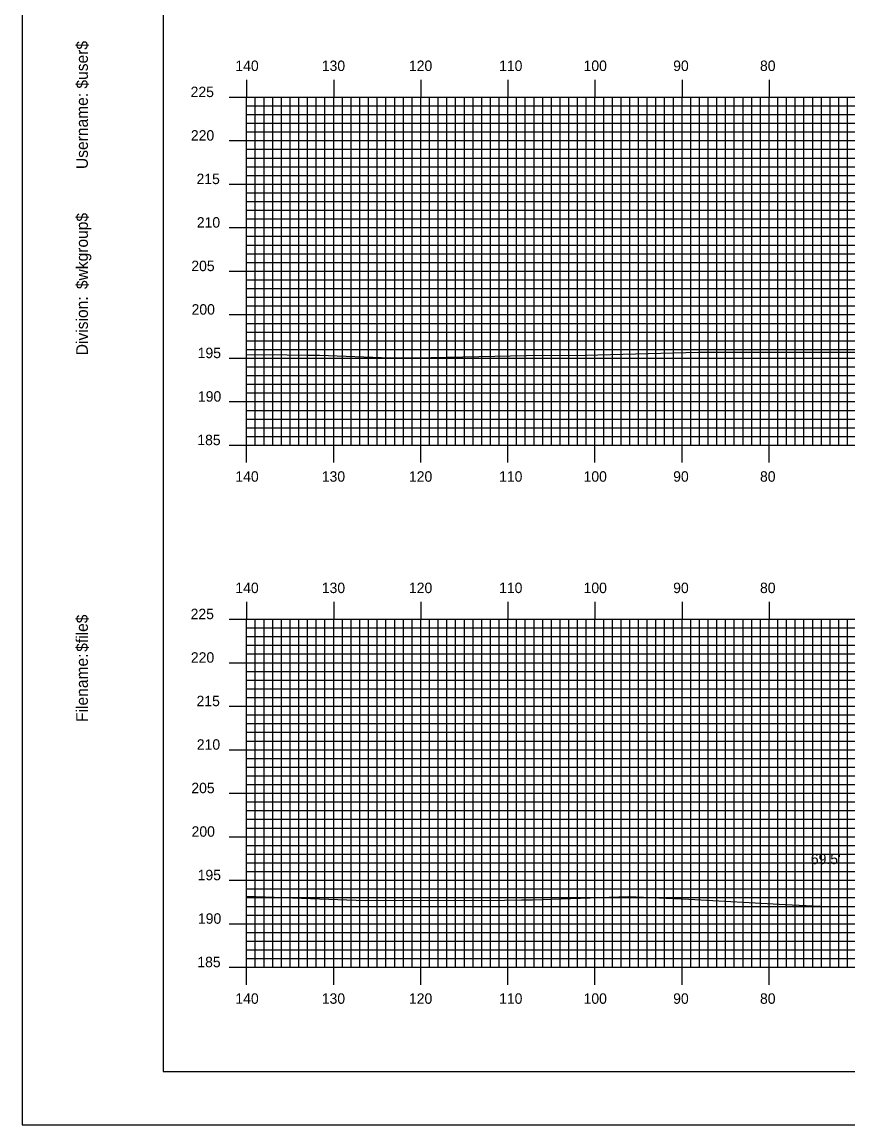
# Model space of a CAD drawing. Extents: x 1811374 to 1811717, y 442591 to 442811.
# Drawn here: x 1811373.6 to 1811468.4, y 442590.5 to 442717.3 of the extents above; entities that cross this region are included whole.
import ezdxf

# ---------------------------------------------------------------- set-up
doc = ezdxf.new("R2010")
doc.units = 0
for name, color, linetype in [('BORDER', 7, 'Continuous'), ('D_Text_Standard', 7, 'Continuous'), ('H_V ANNOTATION', 7, 'Continuous'), ('MAJOR', 7, 'Continuous'), ('MINOR', 7, 'Continuous'), ('PLOT BOUNDARY', 7, 'Continuous'), ('S_Roadway_Centerline', 7, 'Continuous')]:
    doc.layers.add(name, color=color, linetype=linetype)

msp = doc.modelspace()

# ---------------------------------------------------------------- linework, layer by layer
at = {"layer": 'BORDER'}
msp.add_lwpolyline([(1811389.8, 442596.67), (1811709.8, 442596.67), (1811709.8, 442806.67), (1811389.8, 442806.67)], close=True, dxfattribs=at)
at = {"layer": 'MAJOR'}
for p, q in [((1811399.4, 442710.67), (1811399.4, 442708.67)), ((1811409.4, 442710.67), (1811409.4, 442708.67)), ((1811419.4, 442710.67), (1811419.4, 442708.67)), ((1811429.4, 442710.67), (1811429.4, 442708.67)), ((1811439.4, 442710.67), (1811439.4, 442708.67)), ((1811449.4, 442710.67), (1811449.4, 442708.67)), ((1811459.4, 442710.67), (1811459.4, 442708.67)), ((1811397.4, 442708.67), (1811399.4, 442708.67)), ((1811399.4, 442708.67), (1811679.4, 442708.67)), ((1811399.4, 442668.67), (1811399.4, 442708.67)), ((1811399.4, 442668.67), (1811399.4, 442708.67)), ((1811399.4, 442708.67), (1811679.4, 442708.67)), ((1811409.4, 442668.67), (1811409.4, 442708.67)), ((1811419.4, 442668.67), (1811419.4, 442708.67)), ((1811429.4, 442668.67), (1811429.4, 442708.67)), ((1811439.4, 442668.67), (1811439.4, 442708.67)), ((1811449.4, 442668.67), (1811449.4, 442708.67)), ((1811459.4, 442668.67), (1811459.4, 442708.67)), ((1811397.4, 442703.67), (1811399.4, 442703.67)), ((1811399.4, 442703.67), (1811679.4, 442703.67)), ((1811397.4, 442698.67), (1811399.4, 442698.67)), ((1811399.4, 442698.67), (1811679.4, 442698.67)), ((1811397.4, 442693.67), (1811399.4, 442693.67)), ((1811399.4, 442693.67), (1811679.4, 442693.67)), ((1811397.4, 442688.67), (1811399.4, 442688.67)), ((1811399.4, 442688.67), (1811679.4, 442688.67)), ((1811397.4, 442683.67), (1811399.4, 442683.67)), ((1811399.4, 442683.67), (1811679.4, 442683.67)), ((1811397.4, 442678.67), (1811399.4, 442678.67)), ((1811399.4, 442678.67), (1811679.4, 442678.67)), ((1811397.4, 442673.67), (1811399.4, 442673.67)), ((1811399.4, 442673.67), (1811679.4, 442673.67)), ((1811397.4, 442668.67), (1811399.4, 442668.67)), ((1811399.4, 442668.67), (1811679.4, 442668.67)), ((1811399.4, 442668.67), (1811679.4, 442668.67)), ((1811399.4, 442666.66), (1811399.4, 442668.67)), ((1811409.4, 442666.66), (1811409.4, 442668.67)), ((1811419.4, 442666.66), (1811419.4, 442668.67)), ((1811429.4, 442666.66), (1811429.4, 442668.67)), ((1811439.4, 442666.66), (1811439.4, 442668.67)), ((1811449.4, 442666.66), (1811449.4, 442668.67)), ((1811459.4, 442666.66), (1811459.4, 442668.67)), ((1811399.4, 442650.67), (1811399.4, 442648.67)), ((1811409.4, 442650.67), (1811409.4, 442648.67)), ((1811419.4, 442650.67), (1811419.4, 442648.67)), ((1811429.4, 442650.67), (1811429.4, 442648.67)), ((1811439.4, 442650.67), (1811439.4, 442648.67)), ((1811449.4, 442650.67), (1811449.4, 442648.67)), ((1811459.4, 442650.67), (1811459.4, 442648.67)), ((1811397.4, 442648.67), (1811399.4, 442648.67)), ((1811399.4, 442648.67), (1811679.4, 442648.67)), ((1811399.4, 442608.67), (1811399.4, 442648.67)), ((1811399.4, 442608.67), (1811399.4, 442648.67)), ((1811399.4, 442648.67), (1811679.4, 442648.67)), ((1811409.4, 442608.67), (1811409.4, 442648.67)), ((1811419.4, 442608.67), (1811419.4, 442648.67)), ((1811429.4, 442608.67), (1811429.4, 442648.67)), ((1811439.4, 442608.67), (1811439.4, 442648.67)), ((1811449.4, 442608.67), (1811449.4, 442648.67)), ((1811459.4, 442608.67), (1811459.4, 442648.67)), ((1811397.4, 442643.67), (1811399.4, 442643.67)), ((1811399.4, 442643.67), (1811679.4, 442643.67)), ((1811397.4, 442638.67), (1811399.4, 442638.67)), ((1811399.4, 442638.67), (1811679.4, 442638.67)), ((1811397.4, 442633.67), (1811399.4, 442633.67)), ((1811399.4, 442633.67), (1811679.4, 442633.67)), ((1811397.4, 442628.67), (1811399.4, 442628.67)), ((1811399.4, 442628.67), (1811679.4, 442628.67)), ((1811397.4, 442623.67), (1811399.4, 442623.67)), ((1811399.4, 442623.67), (1811679.4, 442623.67)), ((1811397.4, 442618.67), (1811399.4, 442618.67)), ((1811399.4, 442618.67), (1811679.4, 442618.67)), ((1811397.4, 442613.67), (1811399.4, 442613.67)), ((1811399.4, 442613.67), (1811679.4, 442613.67)), ((1811397.4, 442608.67), (1811399.4, 442608.67)), ((1811399.4, 442608.67), (1811679.4, 442608.67)), ((1811399.4, 442608.67), (1811679.4, 442608.67)), ((1811399.4, 442606.66), (1811399.4, 442608.67)), ((1811409.4, 442606.66), (1811409.4, 442608.67)), ((1811419.4, 442606.66), (1811419.4, 442608.67)), ((1811429.4, 442606.66), (1811429.4, 442608.67)), ((1811439.4, 442606.66), (1811439.4, 442608.67)), ((1811449.4, 442606.66), (1811449.4, 442608.67)), ((1811459.4, 442606.66), (1811459.4, 442608.67))]:
    msp.add_line(p, q, dxfattribs=at)
at = {"layer": 'MINOR'}
for p, q in [((1811400.4, 442668.67), (1811400.4, 442708.67)), ((1811401.4, 442668.67), (1811401.4, 442708.67)), ((1811402.4, 442668.67), (1811402.4, 442708.67)), ((1811403.4, 442668.67), (1811403.4, 442708.67)), ((1811404.4, 442668.67), (1811404.4, 442708.67)), ((1811405.4, 442668.67), (1811405.4, 442708.67)), ((1811406.4, 442668.67), (1811406.4, 442708.67)), ((1811407.4, 442668.67), (1811407.4, 442708.67)), ((1811408.4, 442668.67), (1811408.4, 442708.67)), ((1811410.4, 442668.67), (1811410.4, 442708.67)), ((1811411.4, 442668.67), (1811411.4, 442708.67)), ((1811412.4, 442668.67), (1811412.4, 442708.67)), ((1811413.4, 442668.67), (1811413.4, 442708.67)), ((1811414.4, 442668.67), (1811414.4, 442708.67)), ((1811415.4, 442668.67), (1811415.4, 442708.67)), ((1811416.4, 442668.67), (1811416.4, 442708.67)), ((1811417.4, 442668.67), (1811417.4, 442708.67)), ((1811418.4, 442668.67), (1811418.4, 442708.67)), ((1811420.4, 442668.67), (1811420.4, 442708.67)), ((1811421.4, 442668.67), (1811421.4, 442708.67)), ((1811422.4, 442668.67), (1811422.4, 442708.67)), ((1811423.4, 442668.67), (1811423.4, 442708.67)), ((1811424.4, 442668.67), (1811424.4, 442708.67)), ((1811425.4, 442668.67), (1811425.4, 442708.67)), ((1811426.4, 442668.67), (1811426.4, 442708.67)), ((1811427.4, 442668.67), (1811427.4, 442708.67)), ((1811428.4, 442668.67), (1811428.4, 442708.67)), ((1811430.4, 442668.67), (1811430.4, 442708.67)), ((1811431.4, 442668.67), (1811431.4, 442708.67)), ((1811432.4, 442668.67), (1811432.4, 442708.67)), ((1811433.4, 442668.67), (1811433.4, 442708.67)), ((1811434.4, 442668.67), (1811434.4, 442708.67)), ((1811435.4, 442668.67), (1811435.4, 442708.67)), ((1811436.4, 442668.67), (1811436.4, 442708.67)), ((1811437.4, 442668.67), (1811437.4, 442708.67)), ((1811438.4, 442668.67), (1811438.4, 442708.67)), ((1811440.4, 442668.67), (1811440.4, 442708.67)), ((1811441.4, 442668.67), (1811441.4, 442708.67)), ((1811442.4, 442668.67), (1811442.4, 442708.67)), ((1811443.4, 442668.67), (1811443.4, 442708.67)), ((1811444.4, 442668.67), (1811444.4, 442708.67)), ((1811445.4, 442668.67), (1811445.4, 442708.67)), ((1811446.4, 442668.67), (1811446.4, 442708.67)), ((1811447.4, 442668.67), (1811447.4, 442708.67)), ((1811448.4, 442668.67), (1811448.4, 442708.67)), ((1811450.4, 442668.67), (1811450.4, 442708.67)), ((1811451.4, 442668.67), (1811451.4, 442708.67)), ((1811452.4, 442668.67), (1811452.4, 442708.67)), ((1811453.4, 442668.67), (1811453.4, 442708.67)), ((1811454.4, 442668.67), (1811454.4, 442708.67)), ((1811455.4, 442668.67), (1811455.4, 442708.67)), ((1811456.4, 442668.67), (1811456.4, 442708.67)), ((1811457.4, 442668.67), (1811457.4, 442708.67)), ((1811458.4, 442668.67), (1811458.4, 442708.67)), ((1811460.4, 442668.67), (1811460.4, 442708.67)), ((1811461.4, 442668.67), (1811461.4, 442708.67)), ((1811462.4, 442668.67), (1811462.4, 442708.67)), ((1811463.4, 442668.67), (1811463.4, 442708.67)), ((1811464.4, 442668.67), (1811464.4, 442708.67)), ((1811465.4, 442668.67), (1811465.4, 442708.67)), ((1811466.4, 442668.67), (1811466.4, 442708.67)), ((1811467.4, 442668.67), (1811467.4, 442708.67)), ((1811468.4, 442668.67), (1811468.4, 442708.67)), ((1811399.4, 442707.67), (1811679.4, 442707.67)), ((1811399.4, 442707.67), (1811401.41, 442707.67)), ((1811399.4, 442706.67), (1811679.4, 442706.67)), ((1811399.4, 442706.67), (1811401.41, 442706.67)), ((1811399.4, 442705.67), (1811679.4, 442705.67)), ((1811399.4, 442705.67), (1811401.41, 442705.67)), ((1811399.4, 442704.67), (1811679.4, 442704.67)), ((1811399.4, 442704.67), (1811401.41, 442704.67)), ((1811399.4, 442702.67), (1811679.4, 442702.67)), ((1811399.4, 442702.67), (1811401.41, 442702.67)), ((1811399.4, 442701.67), (1811679.4, 442701.67)), ((1811399.4, 442701.67), (1811401.41, 442701.67)), ((1811399.4, 442700.67), (1811679.4, 442700.67)), ((1811399.4, 442700.67), (1811401.41, 442700.67)), ((1811399.4, 442699.67), (1811679.4, 442699.67)), ((1811399.4, 442699.67), (1811401.41, 442699.67)), ((1811399.4, 442697.67), (1811679.4, 442697.67)), ((1811399.4, 442697.67), (1811401.41, 442697.67)), ((1811399.4, 442696.67), (1811679.4, 442696.67)), ((1811399.4, 442696.67), (1811401.41, 442696.67)), ((1811399.4, 442695.67), (1811679.4, 442695.67)), ((1811399.4, 442695.67), (1811401.41, 442695.67)), ((1811399.4, 442694.67), (1811679.4, 442694.67)), ((1811399.4, 442694.67), (1811401.41, 442694.67)), ((1811399.4, 442692.67), (1811679.4, 442692.67)), ((1811399.4, 442692.67), (1811401.41, 442692.67)), ((1811399.4, 442691.67), (1811679.4, 442691.67)), ((1811399.4, 442691.67), (1811401.41, 442691.67)), ((1811399.4, 442690.67), (1811679.4, 442690.67)), ((1811399.4, 442690.67), (1811401.41, 442690.67)), ((1811399.4, 442689.67), (1811679.4, 442689.67)), ((1811399.4, 442689.67), (1811401.41, 442689.67)), ((1811399.4, 442687.67), (1811679.4, 442687.67)), ((1811399.4, 442687.67), (1811401.41, 442687.67)), ((1811399.4, 442686.67), (1811679.4, 442686.67)), ((1811399.4, 442686.67), (1811401.41, 442686.67)), ((1811399.4, 442685.67), (1811679.4, 442685.67)), ((1811399.4, 442685.67), (1811401.41, 442685.67)), ((1811399.4, 442684.67), (1811679.4, 442684.67)), ((1811399.4, 442684.67), (1811401.41, 442684.67)), ((1811399.4, 442682.67), (1811679.4, 442682.67)), ((1811399.4, 442682.67), (1811401.41, 442682.67)), ((1811399.4, 442681.67), (1811679.4, 442681.67)), ((1811399.4, 442681.67), (1811401.41, 442681.67)), ((1811399.4, 442680.67), (1811679.4, 442680.67)), ((1811399.4, 442680.67), (1811401.41, 442680.67)), ((1811399.4, 442679.67), (1811679.4, 442679.67)), ((1811399.4, 442679.67), (1811401.41, 442679.67)), ((1811399.4, 442677.67), (1811679.4, 442677.67)), ((1811399.4, 442677.67), (1811401.41, 442677.67)), ((1811399.4, 442676.67), (1811679.4, 442676.67)), ((1811399.4, 442676.67), (1811401.41, 442676.67)), ((1811399.4, 442675.67), (1811679.4, 442675.67)), ((1811399.4, 442675.67), (1811401.41, 442675.67)), ((1811399.4, 442674.67), (1811679.4, 442674.67)), ((1811399.4, 442674.67), (1811401.41, 442674.67)), ((1811399.4, 442672.67), (1811679.4, 442672.67)), ((1811399.4, 442672.67), (1811401.41, 442672.67)), ((1811399.4, 442671.67), (1811679.4, 442671.67)), ((1811399.4, 442671.67), (1811401.41, 442671.67)), ((1811399.4, 442670.67), (1811679.4, 442670.67)), ((1811399.4, 442670.67), (1811401.41, 442670.67)), ((1811399.4, 442669.67), (1811679.4, 442669.67)), ((1811399.4, 442669.67), (1811401.41, 442669.67)), ((1811400.4, 442608.67), (1811400.4, 442648.67)), ((1811401.4, 442608.67), (1811401.4, 442648.67)), ((1811402.4, 442608.67), (1811402.4, 442648.67)), ((1811403.4, 442608.67), (1811403.4, 442648.67)), ((1811404.4, 442608.67), (1811404.4, 442648.67)), ((1811405.4, 442608.67), (1811405.4, 442648.67)), ((1811406.4, 442608.67), (1811406.4, 442648.67)), ((1811407.4, 442608.67), (1811407.4, 442648.67)), ((1811408.4, 442608.67), (1811408.4, 442648.67)), ((1811410.4, 442608.67), (1811410.4, 442648.67)), ((1811411.4, 442608.67), (1811411.4, 442648.67)), ((1811412.4, 442608.67), (1811412.4, 442648.67)), ((1811413.4, 442608.67), (1811413.4, 442648.67)), ((1811414.4, 442608.67), (1811414.4, 442648.67)), ((1811415.4, 442608.67), (1811415.4, 442648.67)), ((1811416.4, 442608.67), (1811416.4, 442648.67)), ((1811417.4, 442608.67), (1811417.4, 442648.67)), ((1811418.4, 442608.67), (1811418.4, 442648.67)), ((1811420.4, 442608.67), (1811420.4, 442648.67)), ((1811421.4, 442608.67), (1811421.4, 442648.67)), ((1811422.4, 442608.67), (1811422.4, 442648.67)), ((1811423.4, 442608.67), (1811423.4, 442648.67)), ((1811424.4, 442608.67), (1811424.4, 442648.67)), ((1811425.4, 442608.67), (1811425.4, 442648.67)), ((1811426.4, 442608.67), (1811426.4, 442648.67)), ((1811427.4, 442608.67), (1811427.4, 442648.67)), ((1811428.4, 442608.67), (1811428.4, 442648.67)), ((1811430.4, 442608.67), (1811430.4, 442648.67)), ((1811431.4, 442608.67), (1811431.4, 442648.67)), ((1811432.4, 442608.67), (1811432.4, 442648.67)), ((1811433.4, 442608.67), (1811433.4, 442648.67)), ((1811434.4, 442608.67), (1811434.4, 442648.67)), ((1811435.4, 442608.67), (1811435.4, 442648.67)), ((1811436.4, 442608.67), (1811436.4, 442648.67)), ((1811437.4, 442608.67), (1811437.4, 442648.67)), ((1811438.4, 442608.67), (1811438.4, 442648.67)), ((1811440.4, 442608.67), (1811440.4, 442648.67)), ((1811441.4, 442608.67), (1811441.4, 442648.67)), ((1811442.4, 442608.67), (1811442.4, 442648.67)), ((1811443.4, 442608.67), (1811443.4, 442648.67)), ((1811444.4, 442608.67), (1811444.4, 442648.67)), ((1811445.4, 442608.67), (1811445.4, 442648.67)), ((1811446.4, 442608.67), (1811446.4, 442648.67)), ((1811447.4, 442608.67), (1811447.4, 442648.67)), ((1811448.4, 442608.67), (1811448.4, 442648.67)), ((1811450.4, 442608.67), (1811450.4, 442648.67)), ((1811451.4, 442608.67), (1811451.4, 442648.67)), ((1811452.4, 442608.67), (1811452.4, 442648.67)), ((1811453.4, 442608.67), (1811453.4, 442648.67)), ((1811454.4, 442608.67), (1811454.4, 442648.67)), ((1811455.4, 442608.67), (1811455.4, 442648.67)), ((1811456.4, 442608.67), (1811456.4, 442648.67)), ((1811457.4, 442608.67), (1811457.4, 442648.67)), ((1811458.4, 442608.67), (1811458.4, 442648.67)), ((1811460.4, 442608.67), (1811460.4, 442648.67)), ((1811461.4, 442608.67), (1811461.4, 442648.67)), ((1811462.4, 442608.67), (1811462.4, 442648.67)), ((1811463.4, 442608.67), (1811463.4, 442648.67)), ((1811464.4, 442608.67), (1811464.4, 442648.67)), ((1811465.4, 442608.67), (1811465.4, 442648.67)), ((1811466.4, 442608.67), (1811466.4, 442648.67)), ((1811467.4, 442608.67), (1811467.4, 442648.67)), ((1811468.4, 442608.67), (1811468.4, 442648.67)), ((1811399.4, 442647.67), (1811679.4, 442647.67)), ((1811399.4, 442647.67), (1811401.41, 442647.67)), ((1811399.4, 442646.67), (1811679.4, 442646.67)), ((1811399.4, 442646.67), (1811401.41, 442646.67)), ((1811399.4, 442645.67), (1811679.4, 442645.67)), ((1811399.4, 442645.67), (1811401.41, 442645.67)), ((1811399.4, 442644.67), (1811679.4, 442644.67)), ((1811399.4, 442644.67), (1811401.41, 442644.67)), ((1811399.4, 442642.67), (1811679.4, 442642.67)), ((1811399.4, 442642.67), (1811401.41, 442642.67)), ((1811399.4, 442641.67), (1811679.4, 442641.67)), ((1811399.4, 442641.67), (1811401.41, 442641.67)), ((1811399.4, 442640.67), (1811679.4, 442640.67)), ((1811399.4, 442640.67), (1811401.41, 442640.67)), ((1811399.4, 442639.67), (1811679.4, 442639.67)), ((1811399.4, 442639.67), (1811401.41, 442639.67)), ((1811399.4, 442637.67), (1811679.4, 442637.67)), ((1811399.4, 442637.67), (1811401.41, 442637.67)), ((1811399.4, 442636.67), (1811679.4, 442636.67)), ((1811399.4, 442636.67), (1811401.41, 442636.67)), ((1811399.4, 442635.67), (1811679.4, 442635.67)), ((1811399.4, 442635.67), (1811401.41, 442635.67)), ((1811399.4, 442634.67), (1811679.4, 442634.67)), ((1811399.4, 442634.67), (1811401.41, 442634.67)), ((1811399.4, 442632.67), (1811679.4, 442632.67)), ((1811399.4, 442632.67), (1811401.41, 442632.67)), ((1811399.4, 442631.67), (1811679.4, 442631.67)), ((1811399.4, 442631.67), (1811401.41, 442631.67)), ((1811399.4, 442630.67), (1811679.4, 442630.67)), ((1811399.4, 442630.67), (1811401.41, 442630.67)), ((1811399.4, 442629.67), (1811679.4, 442629.67)), ((1811399.4, 442629.67), (1811401.41, 442629.67)), ((1811399.4, 442627.67), (1811679.4, 442627.67)), ((1811399.4, 442627.67), (1811401.41, 442627.67)), ((1811399.4, 442626.67), (1811679.4, 442626.67)), ((1811399.4, 442626.67), (1811401.41, 442626.67)), ((1811399.4, 442625.67), (1811679.4, 442625.67)), ((1811399.4, 442625.67), (1811401.41, 442625.67)), ((1811399.4, 442624.67), (1811679.4, 442624.67)), ((1811399.4, 442624.67), (1811401.41, 442624.67)), ((1811399.4, 442622.67), (1811679.4, 442622.67)), ((1811399.4, 442622.67), (1811401.41, 442622.67)), ((1811399.4, 442621.67), (1811679.4, 442621.67)), ((1811399.4, 442621.67), (1811401.41, 442621.67)), ((1811399.4, 442620.67), (1811679.4, 442620.67)), ((1811399.4, 442620.67), (1811401.41, 442620.67)), ((1811399.4, 442619.67), (1811679.4, 442619.67)), ((1811399.4, 442619.67), (1811401.41, 442619.67)), ((1811399.4, 442617.67), (1811679.4, 442617.67)), ((1811399.4, 442617.67), (1811401.41, 442617.67)), ((1811399.4, 442616.67), (1811679.4, 442616.67)), ((1811399.4, 442616.67), (1811401.41, 442616.67)), ((1811399.4, 442615.67), (1811679.4, 442615.67)), ((1811399.4, 442615.67), (1811401.41, 442615.67)), ((1811399.4, 442614.67), (1811679.4, 442614.67)), ((1811399.4, 442614.67), (1811401.41, 442614.67)), ((1811399.4, 442612.67), (1811679.4, 442612.67)), ((1811399.4, 442612.67), (1811401.41, 442612.67)), ((1811399.4, 442611.67), (1811679.4, 442611.67)), ((1811399.4, 442611.67), (1811401.41, 442611.67)), ((1811399.4, 442610.67), (1811679.4, 442610.67)), ((1811399.4, 442610.67), (1811401.41, 442610.67)), ((1811399.4, 442609.67), (1811679.4, 442609.67)), ((1811399.4, 442609.67), (1811401.41, 442609.67))]:
    msp.add_line(p, q, dxfattribs=at)
at = {"layer": 'PLOT BOUNDARY'}
msp.add_lwpolyline([(1811373.62, 442590.55), (1811713.62, 442590.55), (1811713.62, 442810.55), (1811373.62, 442810.55)], close=True, dxfattribs=at)
at = {"layer": 'S_Roadway_Centerline'}
for points in [[(1811399.4, 442679.1), (1811404.05, 442679.07), (1811406.34, 442679.03), (1811407.77, 442679.01), (1811415.94, 442678.69), (1811418.77, 442678.69), (1811431.55, 442678.97), (1811438.26, 442679.01), (1811451.29, 442679.34), (1811451.39, 442679.34), (1811451.55, 442679.34), (1811469.83, 442679.36)], [(1811399.4, 442616.85), (1811399.44, 442616.85), (1811413.02, 442616.35), (1811429.03, 442616.36), (1811430.97, 442616.4), (1811432.23, 442616.43), (1811443.24, 442616.81), (1811450.17, 442616.51), (1811461.23, 442615.87), (1811466.87, 442615.61), (1811469.67, 442615.64)]]:
    msp.add_lwpolyline(points, dxfattribs=at)

# ---------------------------------------------------------------- texts
at = {"layer": 'BORDER'}
for s, p in [('$user$', (1811381.17, 442709.65)), ('Username:', (1811381.17, 442700.4)), ('$wkgroup$', (1811381.17, 442686.6)), ('Division:', (1811381.17, 442679)), ('$file$', (1811381.17, 442644.92)), ('Filename:', (1811381.17, 442636.86))]:
    msp.add_text(s, height=1.339, rotation=90, dxfattribs=at).set_placement(p)
at = {"layer": 'D_Text_Standard'}
msp.add_text("69.5'", height=1.2, dxfattribs=at).set_placement((1811464.19, 442620.52))
at = {"layer": 'H_V ANNOTATION'}
for s, p in [('140', (1811398.11, 442711.67)), ('130', (1811408.03, 442711.67)), ('120', (1811418.04, 442711.67)), ('110', (1811428.39, 442711.67)), ('100', (1811438.09, 442711.67)), ('90', (1811448.38, 442711.67)), ('80', (1811458.35, 442711.67)), ('225', (1811392.97, 442708.67)), ('220', (1811393, 442703.67)), ('215', (1811393.65, 442698.67)), ('210', (1811393.68, 442693.67)), ('205', (1811393.05, 442688.67)), ('200', (1811393.08, 442683.67)), ('195', (1811393.78, 442678.67)), ('190', (1811393.81, 442673.67)), ('185', (1811393.74, 442668.67)), ('140', (1811398.11, 442664.47)), ('130', (1811408.03, 442664.47)), ('120', (1811418.04, 442664.47)), ('110', (1811428.39, 442664.47)), ('100', (1811438.09, 442664.47)), ('90', (1811448.38, 442664.47)), ('80', (1811458.35, 442664.47)), ('140', (1811398.11, 442651.67)), ('130', (1811408.03, 442651.67)), ('120', (1811418.04, 442651.67)), ('110', (1811428.39, 442651.67)), ('100', (1811438.09, 442651.67)), ('90', (1811448.38, 442651.67)), ('80', (1811458.35, 442651.67)), ('225', (1811392.97, 442648.67)), ('220', (1811393, 442643.67)), ('215', (1811393.65, 442638.67)), ('210', (1811393.68, 442633.67)), ('205', (1811393.05, 442628.67)), ('200', (1811393.08, 442623.67)), ('195', (1811393.78, 442618.67)), ('190', (1811393.81, 442613.67)), ('185', (1811393.74, 442608.67)), ('140', (1811398.11, 442604.47)), ('130', (1811408.03, 442604.47)), ('120', (1811418.04, 442604.47)), ('110', (1811428.39, 442604.47)), ('100', (1811438.09, 442604.47)), ('90', (1811448.38, 442604.47)), ('80', (1811458.35, 442604.47))]:
    msp.add_text(s, height=1.2, dxfattribs=at).set_placement(p)
at = {"layer": 'MAJOR'}
for p in [(1811399.39, 442668.67), (1811399.39, 442608.67)]:
    msp.add_text('-', height=0.012, dxfattribs=at).set_placement(p)

doc.saveas('drawing.dxf')
